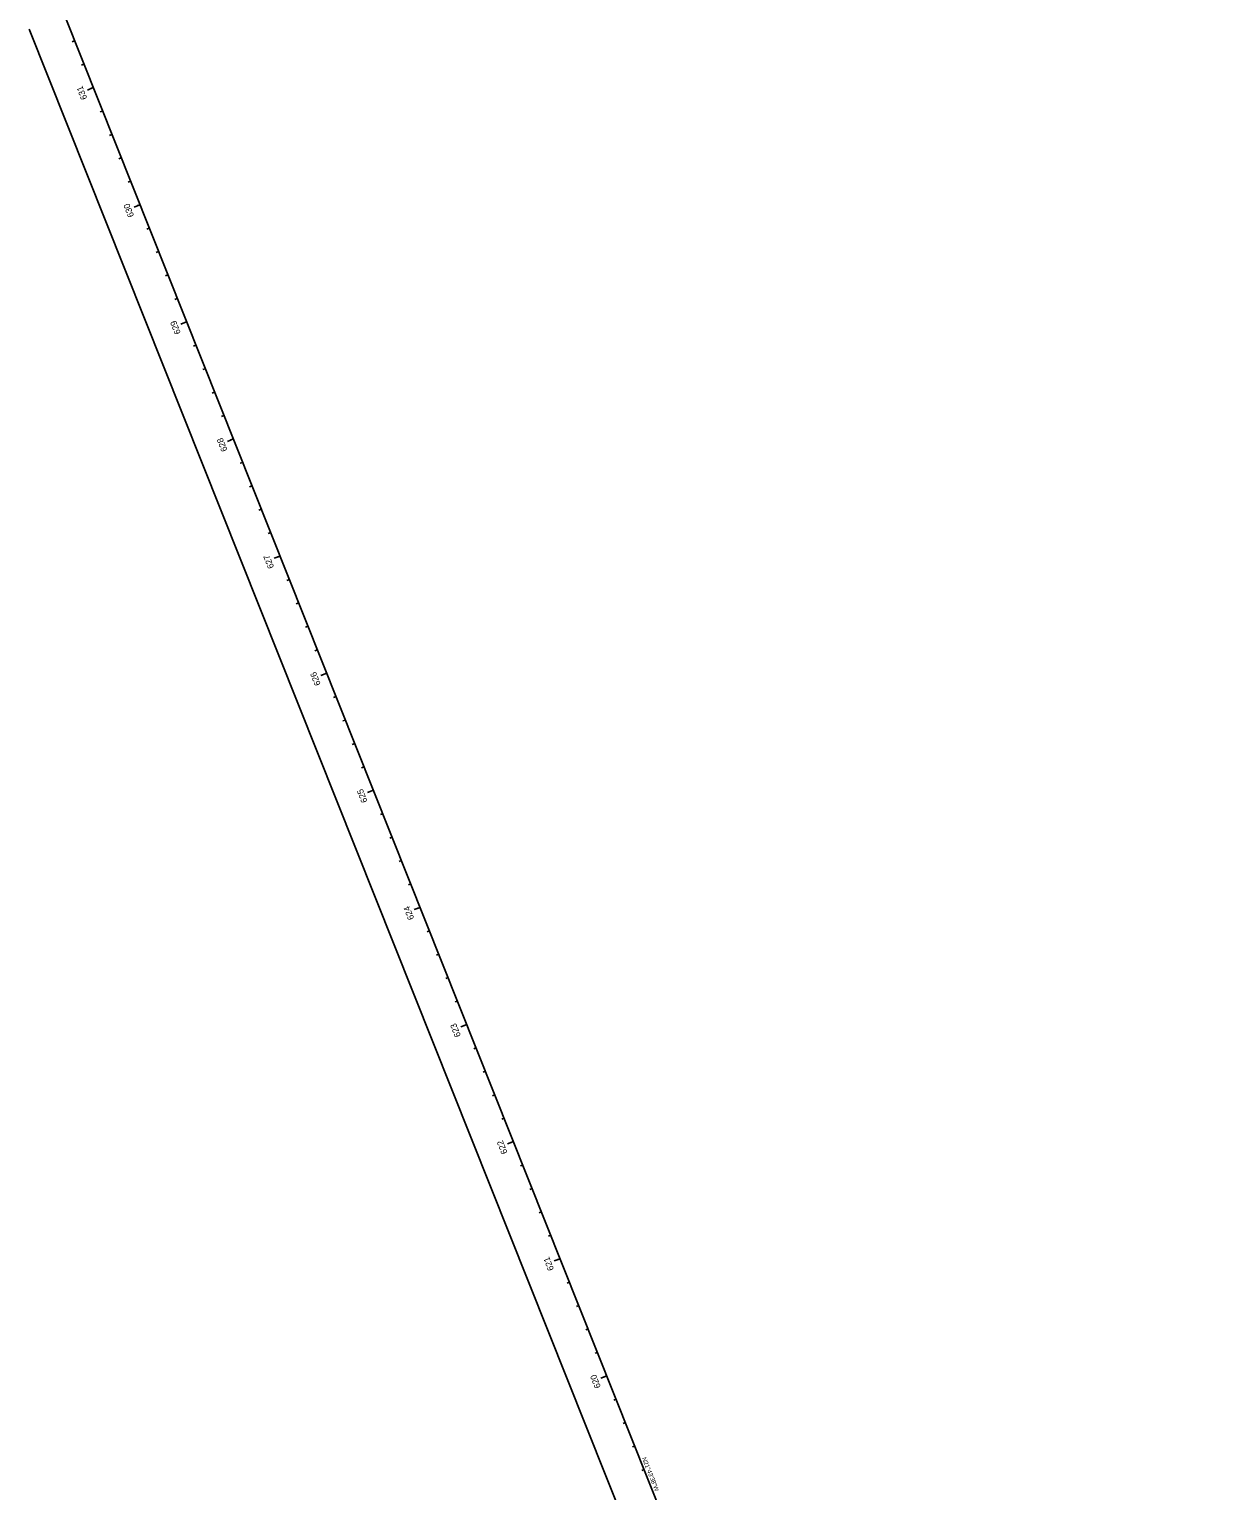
# Model space of a CAD drawing. Extents: x 2003883 to 2007688, y 399149 to 412300.
# Drawn here: x 2004016 to 2004968, y 409083 to 410243 of the extents above; entities that cross this region are included whole.
import ezdxf

# ---------------------------------------------------------------- set-up
doc = ezdxf.new("R2010")
doc.units = 0
for name, color, linetype in [('BaselineSurvey', 7, 'Continuous'), ('ConstLines', 7, 'Continuous'), ('Default', 7, 'Continuous'), ('TextAlgnStation100', 7, 'Continuous'), ('TextAlgnStation1000', 7, 'Continuous'), ('TextAlgnStation500', 7, 'Continuous'), ('TextAlgnTangent', 7, 'Continuous'), ('TextAlgnTicks100', 7, 'Continuous'), ('TextAlgnTicks1000', 7, 'Continuous'), ('TextAlgnTicks500', 7, 'Continuous'), ('TextAlgnTicks5000', 7, 'Continuous')]:
    doc.layers.add(name, color=color, linetype=linetype)

msp = doc.modelspace()

# ---------------------------------------------------------------- linework, layer by layer
at = {"layer": 'BaselineSurvey'}
msp.add_line((2004967.7, 407935), (2004043.6, 410254), dxfattribs=at)
at = {"layer": 'ConstLines'}
msp.add_line((2004939.8, 407923.9), (2004015.7, 410242.9), dxfattribs=at)
at = {"layer": 'Default'}
msp.add_line((2004967.7, 407935), (2004043.6, 410254), dxfattribs=at)
at = {"layer": 'TextAlgnTicks100'}
for p, q in [((2004051.7, 410233.7), (2004049.8, 410233)), ((2004059.1, 410215.2), (2004057.2, 410214.4)), ((2004066.5, 410196.6), (2004061.9, 410194.7)), ((2004073.9, 410178), (2004072, 410177.3)), ((2004081.3, 410159.4), (2004079.4, 410158.7)), ((2004088.7, 410140.8), (2004086.8, 410140.1)), ((2004096.1, 410122.3), (2004094.3, 410121.5)), ((2004103.5, 410103.7), (2004098.9, 410101.8)), ((2004110.9, 410085.1), (2004109.1, 410084.4)), ((2004118.3, 410066.5), (2004116.5, 410065.8)), ((2004125.7, 410048), (2004123.9, 410047.2)), ((2004133.1, 410029.4), (2004131.3, 410028.6)), ((2004140.5, 410010.8), (2004135.9, 410008.9)), ((2004147.9, 409992.2), (2004146.1, 409991.5)), ((2004155.3, 409973.6), (2004153.5, 409972.9)), ((2004162.7, 409955.1), (2004160.9, 409954.3)), ((2004170.1, 409936.5), (2004168.3, 409935.7)), ((2004177.6, 409917.9), (2004172.9, 409916)), ((2004185, 409899.3), (2004183.1, 409898.6)), ((2004192.4, 409880.7), (2004190.5, 409880)), ((2004199.8, 409862.2), (2004197.9, 409861.4)), ((2004207.2, 409843.6), (2004205.3, 409842.8)), ((2004214.6, 409825), (2004209.9, 409823.2)), ((2004222, 409806.4), (2004220.1, 409805.7)), ((2004229.4, 409787.8), (2004227.5, 409787.1)), ((2004236.8, 409769.3), (2004234.9, 409768.5)), ((2004244.2, 409750.7), (2004242.3, 409749.9)), ((2004251.6, 409732.1), (2004246.9, 409730.3)), ((2004259, 409713.5), (2004257.1, 409712.8)), ((2004266.4, 409694.9), (2004264.5, 409694.2)), ((2004273.8, 409676.4), (2004271.9, 409675.6)), ((2004281.2, 409657.8), (2004279.3, 409657.1)), ((2004288.6, 409639.2), (2004284, 409637.4)), ((2004296, 409620.6), (2004294.2, 409619.9)), ((2004303.4, 409602.1), (2004301.6, 409601.3)), ((2004310.8, 409583.5), (2004309, 409582.7)), ((2004318.2, 409564.9), (2004316.4, 409564.2)), ((2004325.6, 409546.3), (2004321, 409544.5)), ((2004333, 409527.7), (2004331.2, 409527)), ((2004340.4, 409509.2), (2004338.6, 409508.4)), ((2004347.8, 409490.6), (2004346, 409489.8)), ((2004355.2, 409472), (2004353.4, 409471.3)), ((2004362.6, 409453.4), (2004358, 409451.6)), ((2004370, 409434.8), (2004368.2, 409434.1)), ((2004377.5, 409416.3), (2004375.6, 409415.5)), ((2004384.9, 409397.7), (2004383, 409396.9)), ((2004392.3, 409379.1), (2004390.4, 409378.4)), ((2004399.7, 409360.5), (2004395, 409358.7)), ((2004407.1, 409341.9), (2004405.2, 409341.2)), ((2004414.5, 409323.4), (2004412.6, 409322.6)), ((2004421.9, 409304.8), (2004420, 409304)), ((2004429.3, 409286.2), (2004427.4, 409285.5)), ((2004436.7, 409267.6), (2004432, 409265.8)), ((2004444.1, 409249), (2004442.2, 409248.3)), ((2004451.5, 409230.5), (2004449.6, 409229.7)), ((2004458.9, 409211.9), (2004457, 409211.2)), ((2004466.3, 409193.3), (2004464.4, 409192.6)), ((2004473.7, 409174.7), (2004469.1, 409172.9)), ((2004481.1, 409156.2), (2004479.2, 409155.4)), ((2004488.5, 409137.6), (2004486.6, 409136.8)), ((2004495.9, 409119), (2004494.1, 409118.3)), ((2004503.3, 409100.4), (2004501.5, 409099.7))]:
    msp.add_line(p, q, dxfattribs=at)
at = {"layer": 'TextAlgnTicks1000'}
for p, q in [((2004103.5, 410103.7), (2004098.9, 410101.8)), ((2004177.6, 409917.9), (2004175.7, 409917.2)), ((2004251.6, 409732.1), (2004249.7, 409731.4)), ((2004325.6, 409546.3), (2004323.8, 409545.6)), ((2004399.7, 409360.5), (2004397.8, 409359.8)), ((2004473.7, 409174.7), (2004469.1, 409172.9))]:
    msp.add_line(p, q, dxfattribs=at)
at = {"layer": 'TextAlgnTicks500'}
for p, q in [((2004066.5, 410196.6), (2004064.6, 410195.8)), ((2004103.5, 410103.7), (2004098.9, 410101.8)), ((2004140.5, 410010.8), (2004138.7, 410010.1)), ((2004177.6, 409917.9), (2004175.7, 409917.2)), ((2004214.6, 409825), (2004212.7, 409824.3)), ((2004251.6, 409732.1), (2004249.7, 409731.4)), ((2004288.6, 409639.2), (2004284, 409637.4)), ((2004325.6, 409546.3), (2004323.8, 409545.6)), ((2004362.6, 409453.4), (2004360.8, 409452.7)), ((2004399.7, 409360.5), (2004397.8, 409359.8)), ((2004436.7, 409267.6), (2004434.8, 409266.9)), ((2004473.7, 409174.7), (2004469.1, 409172.9))]:
    msp.add_line(p, q, dxfattribs=at)
at = {"layer": 'TextAlgnTicks5000'}
for p, q in [((2004103.5, 410103.7), (2004101.7, 410103)), ((2004473.7, 409174.7), (2004471.8, 409174))]:
    msp.add_line(p, q, dxfattribs=at)

# ---------------------------------------------------------------- texts
at = {"layer": 'TextAlgnStation100'}
for s, p in [('631', (2004061.8, 410188.1)), ('630', (2004099, 410094.9)), ('629', (2004136, 410002)), ('628', (2004173, 409909)), ('627', (2004210, 409816.2)), ('626', (2004247, 409723.3)), ('625', (2004284.1, 409630.4)), ('624', (2004321.1, 409537.5)), ('623', (2004358.1, 409444.5)), ('622', (2004395.1, 409351.7)), ('621', (2004432, 409259.2)), ('620', (2004469.1, 409165.9))]:
    msp.add_text(s, height=4.98, rotation=111.7271, dxfattribs=at).set_placement(p)
at = {"layer": 'TextAlgnStation1000'}
for s, p in [('630', (2004099, 410094.9)), ('620', (2004469.1, 409165.9))]:
    msp.add_text(s, height=4.98, rotation=111.7271, dxfattribs=at).set_placement(p)
at = {"layer": 'TextAlgnStation500'}
for s, p in [('630', (2004099, 410094.9)), ('625', (2004284.1, 409630.4)), ('620', (2004469.1, 409165.9))]:
    msp.add_text(s, height=4.98, rotation=111.7271, dxfattribs=at).set_placement(p)
at = {"layer": 'TextAlgnTangent'}
msp.add_text('N21°43\'38"W', height=3.48, rotation=291.7271, dxfattribs=at).set_placement((2004501.5, 409109.3))

doc.saveas('drawing.dxf')
